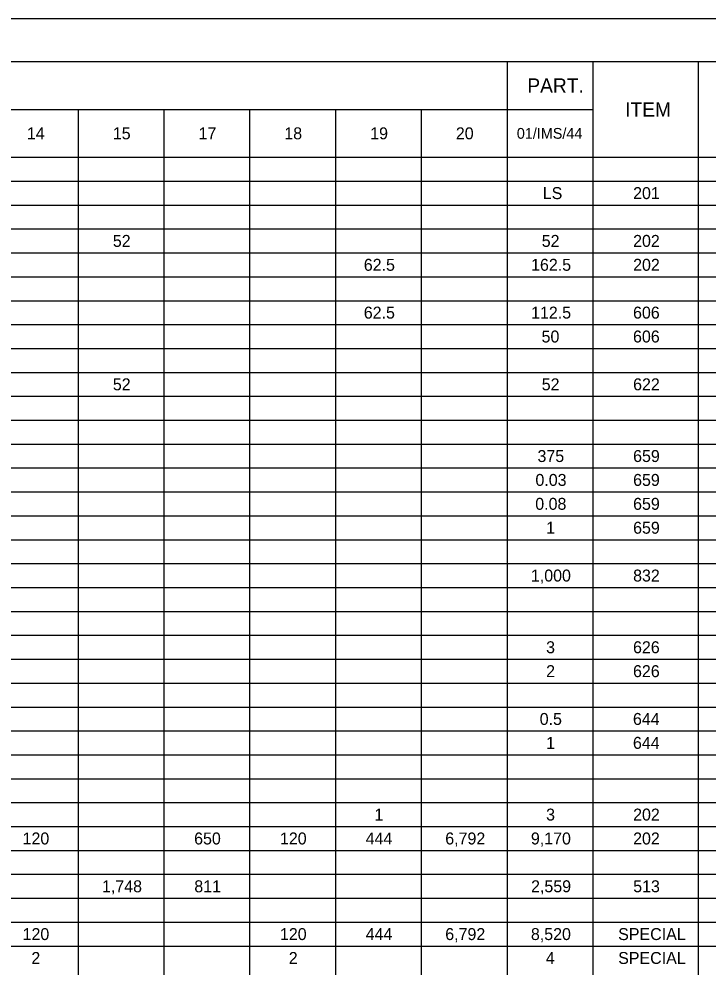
# Model space of a CAD drawing. Extents: x 0 to 34, y 0 to 22.
# Drawn here: x 8.85 to 16.92, y 10.89 to 22 of the extents above; entities that cross this region are included whole.
import ezdxf

# ---------------------------------------------------------------- set-up
doc = ezdxf.new("R2010")
doc.units = 0
for name, color, linetype in [('SH_Border', 7, 'Continuous'), ('SH_Cut_Line', 7, 'Continuous'), ('SH_Data', 7, 'Continuous'), ('SH_Text', 7, 'Continuous')]:
    doc.layers.add(name, color=color, linetype=linetype)

msp = doc.modelspace()

# ---------------------------------------------------------------- linework, layer by layer
at = {"layer": 'SH_Border'}
msp.add_lwpolyline([(1.5, 21.5), (33.5, 21.5), (33.5, 0.5), (1.5, 0.5)], close=True, dxfattribs=at)
at = {"layer": 'SH_Cut_Line'}
msp.add_lwpolyline([(0, 0), (34, 0), (34, 22), (0, 22)], close=True, dxfattribs=at)
at = {"layer": 'SH_Data'}
for p, q in [((1.5, 21.5), (32.004, 21.5)), ((14.561, 21.5), (14.561, 0.5)), ((15.566, 21.5), (15.566, 0.5)), ((16.801, 21.5), (16.801, 0.5)), ((1.5, 20.94), (15.566, 20.94)), ((9.538, 20.94), (9.538, 0.5)), ((10.542, 20.94), (10.542, 0.5)), ((11.547, 20.94), (11.547, 0.5)), ((12.552, 20.94), (12.552, 0.5)), ((13.556, 20.94), (13.556, 0.5)), ((1.5, 20.38), (32.004, 20.38)), ((1.5, 20.1), (32.004, 20.1)), ((1.5, 19.82), (32.004, 19.82)), ((1.5, 19.54), (32.004, 19.54)), ((1.5, 19.26), (32.004, 19.26)), ((1.5, 18.98), (32.004, 18.98)), ((1.5, 18.7), (32.004, 18.7)), ((1.5, 18.42), (32.004, 18.42)), ((1.5, 18.14), (32.004, 18.14)), ((1.5, 17.86), (32.004, 17.86)), ((1.5, 17.58), (32.004, 17.58)), ((1.5, 17.3), (32.004, 17.3)), ((1.5, 17.02), (32.004, 17.02)), ((1.5, 16.74), (32.004, 16.74)), ((1.5, 16.46), (32.004, 16.46)), ((1.5, 16.18), (32.004, 16.18)), ((1.5, 15.9), (32.004, 15.9)), ((1.5, 15.62), (32.004, 15.62)), ((1.5, 15.34), (32.004, 15.34)), ((1.5, 15.06), (32.004, 15.06)), ((1.5, 14.78), (32.004, 14.78)), ((1.5, 14.5), (32.004, 14.5)), ((1.5, 14.22), (32.004, 14.22)), ((1.5, 13.94), (32.004, 13.94)), ((1.5, 13.66), (32.004, 13.66)), ((1.5, 13.38), (32.004, 13.38)), ((1.5, 13.1), (32.004, 13.1)), ((1.5, 12.82), (32.004, 12.82)), ((1.5, 12.54), (32.004, 12.54)), ((1.5, 12.26), (32.004, 12.26)), ((1.5, 11.98), (32.004, 11.98)), ((1.5, 11.7), (32.004, 11.7)), ((1.5, 11.42), (32.004, 11.42)), ((1.5, 11.14), (32.004, 11.14))]:
    msp.add_line(p, q, dxfattribs=at)

# ---------------------------------------------------------------- texts
at = {"layer": 'SH_Text'}
for s, height, p in [('PART.', 0.168, (14.799, 21.136)), ('ITEM', 0.168, (15.945, 20.856)), ('14', 0.14, (8.938, 20.59)), ('15', 0.14, (9.945, 20.59)), ('17', 0.14, (10.949, 20.59)), ('18', 0.14, (11.953, 20.59)), ('19', 0.14, (12.959, 20.59)), ('20', 0.14, (13.962, 20.59)), ('01/IMS/44', 0.126, (14.676, 20.597)), ('LS', 0.14, (14.98, 19.89)), ('201', 0.14, (16.038, 19.89)), ('52', 0.14, (9.945, 19.33)), ('52', 0.14, (14.968, 19.33)), ('202', 0.14, (16.038, 19.33)), ('62.5', 0.14, (12.884, 19.05)), ('162.5', 0.14, (14.843, 19.05)), ('202', 0.14, (16.038, 19.05)), ('62.5', 0.14, (12.884, 18.49)), ('112.5', 0.14, (14.843, 18.49)), ('606', 0.14, (16.037, 18.49)), ('50', 0.14, (14.966, 18.21)), ('606', 0.14, (16.037, 18.21)), ('52', 0.14, (9.945, 17.65)), ('52', 0.14, (14.968, 17.65)), ('622', 0.14, (16.038, 17.65)), ('375', 0.14, (14.918, 16.81)), ('659', 0.14, (16.038, 16.81)), ('0.03', 0.14, (14.894, 16.53)), ('659', 0.14, (16.038, 16.53)), ('0.08', 0.14, (14.892, 16.25)), ('659', 0.14, (16.038, 16.25)), ('1', 0.14, (15.019, 15.97)), ('659', 0.14, (16.038, 15.97)), ('1,000', 0.14, (14.841, 15.41)), ('832', 0.14, (16.038, 15.41)), ('3', 0.14, (15.019, 14.57)), ('626', 0.14, (16.037, 14.57)), ('2', 0.14, (15.019, 14.29)), ('626', 0.14, (16.037, 14.29)), ('0.5', 0.14, (14.944, 13.73)), ('644', 0.14, (16.036, 13.73)), ('1', 0.14, (15.019, 13.45)), ('644', 0.14, (16.036, 13.45)), ('1', 0.14, (13.009, 12.61)), ('3', 0.14, (15.019, 12.61)), ('202', 0.14, (16.038, 12.61)), ('120', 0.14, (8.888, 12.33)), ('650', 0.14, (10.897, 12.33)), ('120', 0.14, (11.902, 12.33)), ('444', 0.14, (12.906, 12.33)), ('6,792', 0.14, (13.838, 12.33)), ('9,170', 0.14, (14.841, 12.33)), ('202', 0.14, (16.038, 12.33)), ('1,748', 0.14, (9.818, 11.77)), ('811', 0.14, (10.899, 11.77)), ('2,559', 0.14, (14.843, 11.77)), ('513', 0.14, (16.039, 11.77)), ('120', 0.14, (8.888, 11.21)), ('120', 0.14, (11.902, 11.21)), ('444', 0.14, (12.906, 11.21)), ('6,792', 0.14, (13.838, 11.21)), ('8,520', 0.14, (14.841, 11.21)), ('SPECIAL', 0.14, (15.863, 11.21)), ('2', 0.14, (8.991, 10.93)), ('2', 0.14, (12.005, 10.93)), ('4', 0.14, (15.016, 10.93)), ('SPECIAL', 0.14, (15.863, 10.93))]:
    msp.add_text(s, height=height, dxfattribs=at).set_placement(p)

doc.saveas('drawing.dxf')
